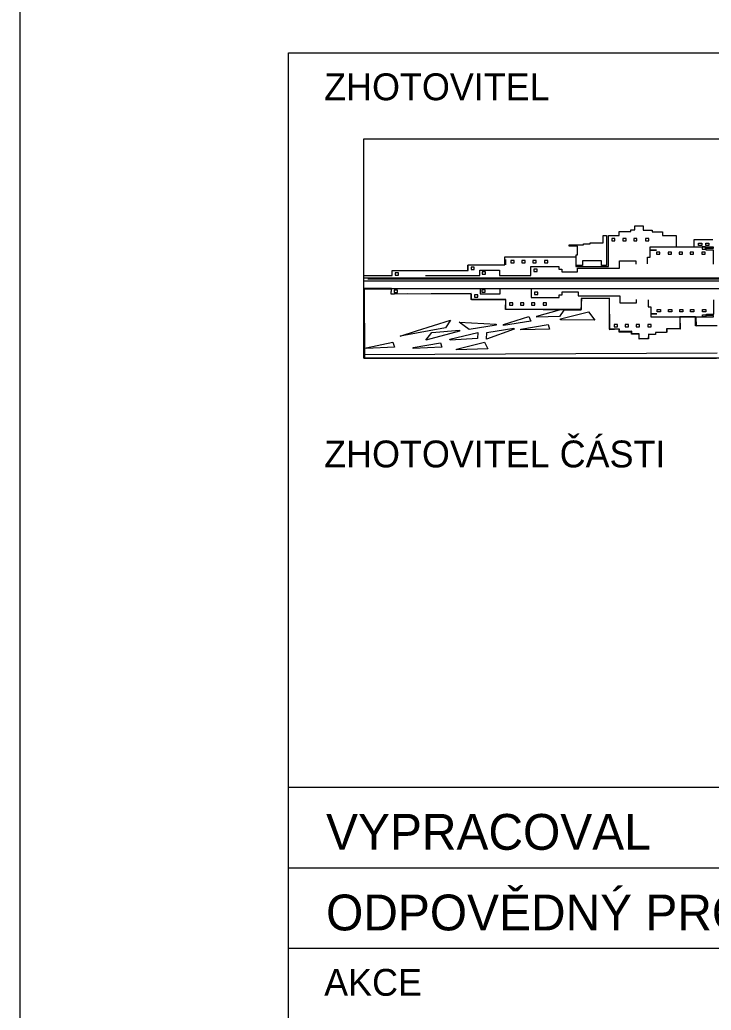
# Model space of a CAD drawing. Extents: x -740053 to -737517, y -1033516 to -1032488.
# Drawn here: x -738610.01 to -738590.71, y -1032656.95 to -1032629.3 of the extents above; entities that cross this region are included whole.
import ezdxf

# ---------------------------------------------------------------- set-up
doc = ezdxf.new("R2010")
doc.units = 0
for name, color, linetype in [('Predmety bez rozlišeni', 7, 'Continuous'), ('promika-formát', 7, 'Continuous'), ('promika-rozp', 7, 'Continuous')]:
    doc.layers.add(name, color=color, linetype=linetype)

# ---------------------------------------------------------------- blocks, each defined once
blk = doc.blocks.new('onegast')
for p, q in [((6.825, 5.723), (6.825, 6.082)), ((9.252, 6.105), (9.252, 6.463)), ((9.309, 6.102), (9.309, 6.46)), ((0.046, 5.264), (49.513, 5.263)), ((0.278, 5.186), (49.435, 5.186)), ((0.046, 5.075), (49.427, 5.075)), ((0.046, 4.561), (49.435, 4.561))]:
    blk.add_line(p, q)
for points in [[(0, 14.352), (49.53, 14.352), (49.53, 0), (0, 0)], [(21.914, 7.53), (22.13, 7.53), (22.13, 7.378), (21.914, 7.378)], [(22.377, 7.53), (22.593, 7.53), (22.593, 7.378), (22.377, 7.378)], [(19.161, 6.799), (19.377, 6.799), (19.377, 6.95), (19.161, 6.95)], [(9.139, 2.21), (10.813, 2.729), (10.929, 2.436), (9.143, 2.148)], [(12.874, 2.574), (14.701, 3.028), (15.132, 2.483), (12.879, 2.512)], [(19.195, 3.182), (19.411, 3.182), (19.411, 3.031), (19.195, 3.031)], [(3.464, 1.792), (5.689, 2.483), (5.353, 1.985), (2.388, 1.451)], [(6.257, 2.359), (8.663, 2.239), (8.678, 2.175), (6.892, 1.886)], [(8.049, 1.674), (9.825, 1.965), (9.84, 1.9), (8.039, 1.247)], [(10.285, 1.911), (12.061, 2.202), (12.15, 1.899), (10.289, 1.849)], [(4.449, 1.687), (6.263, 1.842), (6.277, 1.778), (4.06, 1.174)], [(5.644, 1.239), (7.471, 1.693), (7.457, 1.283), (5.649, 1.176)], [(0.161, 0.692), (1.912, 1.059), (2.012, 0.718), (0.165, 0.63)], [(3.24, 0.71), (5.016, 1), (5.119, 0.715), (3.244, 0.648)], [(6.077, 0.602), (7.903, 1.057), (8.126, 0.622), (6.081, 0.54)]]:
    blk.add_lwpolyline(points, close=True)
for points in [[(0.046, 5.405), (1.862, 5.405), (1.862, 5.731), (6.84, 5.731), (6.84, 6.109), (9.238, 6.109), (9.238, 6.643), (13.878, 6.643), (13.878, 6.005), (16.015, 6.005), (16.015, 8.023), (16.706, 8.023), (16.706, 8.284), (17.475, 8.284), (17.475, 8.401), (17.749, 8.401), (17.749, 8.662), (18.296, 8.662), (18.296, 8.388), (18.879, 8.388), (18.879, 8.272), (19.556, 8.272), (19.556, 8.037), (20.443, 8.037), (20.443, 7.282), (21.616, 7.282), (21.616, 7.764), (22.841, 7.764)], [(14.328, 6.074), (13.905, 6.074), (13.905, 6.765), (14, 6.765), (14, 7.326), (13.453, 7.326), (13.453, 7.425), (14.378, 7.425), (14.378, 7.475), (14.825, 7.475), (14.825, 7.544), (15.233, 7.544), (15.273, 7.544), (15.68, 7.544), (15.68, 8.021), (15.879, 8.021), (15.879, 6.074), (15.571, 6.074), (15.571, 6.362), (14.328, 6.362), (14.328, 6.074)], [(16.228, 7.685), (16.444, 7.685), (16.444, 7.836), (16.228, 7.836), (16.228, 7.685)], [(16.952, 7.685), (17.168, 7.685), (17.168, 7.836), (16.952, 7.836), (16.952, 7.685)], [(17.666, 7.685), (17.882, 7.685), (17.882, 7.836), (17.666, 7.836), (17.666, 7.685)], [(18.439, 7.685), (18.655, 7.685), (18.655, 7.836), (18.439, 7.836), (18.439, 7.685)], [(18.576, 6.169), (18.576, 6.617), (18.746, 6.617), (18.746, 7.081), (19.149, 7.081), (19.149, 7.081), (18.746, 7.081), (18.746, 7.282), (22.862, 7.282), (22.862, 7.282), (22.862, 7.183), (22.396, 7.183), (22.396, 7.088), (22.871, 7.088), (22.871, 6.157)], [(22.141, 7.131), (22.357, 7.131), (22.357, 7.282), (22.141, 7.282), (22.141, 7.131)], [(19.919, 6.799), (20.135, 6.799), (20.135, 6.95), (19.919, 6.95), (19.919, 6.799)], [(20.644, 6.799), (20.86, 6.799), (20.86, 6.95), (20.644, 6.95), (20.644, 6.799)], [(21.358, 6.799), (21.574, 6.799), (21.574, 6.95), (21.358, 6.95), (21.358, 6.799)], [(22.13, 6.799), (22.346, 6.799), (22.346, 6.95), (22.13, 6.95), (22.13, 6.799)], [(4.051, 5.42), (7.596, 5.42), (7.596, 5.765), (8.897, 5.765), (8.897, 5.42), (10.933, 5.42), (10.933, 6.01), (12.761, 6.01), (12.761, 5.826), (12.957, 5.826), (12.957, 5.643), (14, 5.643), (14, 5.888), (16.736, 5.888), (16.736, 6.366), (17.815, 6.366), (17.815, 6.145)], [(7.024, 5.813), (7.24, 5.813), (7.24, 5.964), (7.024, 5.964), (7.024, 5.813)], [(9.628, 6.243), (9.844, 6.243), (9.844, 6.394), (9.628, 6.394), (9.628, 6.243)], [(10.353, 6.243), (10.569, 6.243), (10.569, 6.394), (10.353, 6.394), (10.353, 6.243)], [(11.067, 6.243), (11.283, 6.243), (11.283, 6.394), (11.067, 6.394), (11.067, 6.243)], [(11.131, 5.681), (11.348, 5.681), (11.348, 5.832), (11.131, 5.832), (11.131, 5.681)], [(11.839, 6.243), (12.055, 6.243), (12.055, 6.394), (11.839, 6.394), (11.839, 6.243)], [(2.06, 5.439), (2.276, 5.439), (2.276, 5.591), (2.06, 5.591), (2.06, 5.439)], [(7.749, 5.505), (7.965, 5.505), (7.965, 5.656), (7.749, 5.656), (7.749, 5.505)], [(0.036, 4.579), (0.065, 0.028), (23.119, 0.038)], [(23.133, 2.114), (21.714, 2.114), (21.714, 2.699), (20.694, 2.699), (20.694, 1.928), (19.819, 1.928), (19.819, 1.69), (19.103, 1.69), (19.103, 1.544), (18.625, 1.544), (18.625, 1.266), (18.029, 1.266), (18.029, 1.57), (17.525, 1.57), (17.525, 1.716), (16.716, 1.716), (16.716, 1.902), (16.093, 1.902), (16.093, 3.915), (14.237, 3.915), (14.237, 3.187), (9.292, 3.187), (9.292, 3.849), (7.039, 3.849), (7.039, 4.233), (1.802, 4.196), (1.811, 4.57), (0.036, 4.579)], [(4.084, 4.561), (7.63, 4.561), (7.63, 4.216), (8.93, 4.216), (8.93, 4.561), (10.967, 4.561), (10.967, 3.971), (12.794, 3.971), (12.794, 4.155), (12.991, 4.155), (12.991, 4.339), (14.034, 4.339), (14.034, 4.094), (16.769, 4.094), (16.769, 3.616), (17.849, 3.616), (17.849, 3.836)], [(0.02, 0.014), (23.093, 0.002)], [(23.125, 2.114), (22.3, 2.114), (21.766, 2.106), (21.766, 2.114), (21.714, 2.114), (21.714, 2.69), (20.694, 2.699), (20.694, 2.513), (20.708, 1.897), (19.841, 1.924), (19.841, 1.714), (19.819, 1.714), (19.819, 1.69), (19.163, 1.69), (19.103, 1.687), (19.103, 1.544), (18.635, 1.544), (18.625, 1.386), (18.625, 1.266), (18.256, 1.266), (18.026, 1.258), (18.017, 1.57), (17.525, 1.57), (17.525, 1.716), (16.716, 1.716), (16.716, 1.896), (16.101, 1.86), (16.101, 1.902), (16.093, 1.902), (16.093, 2.719), (16.083, 3.915), (14.514, 3.915), (14.249, 3.911), (14.237, 3.714), (14.237, 3.187), (14.206, 3.187), (14.203, 3.146), (13.089, 3.156), (12.812, 2.735), (11.338, 2.693), (11.334, 2.755), (12.803, 3.159), (9.776, 3.187), (9.292, 3.187), (9.292, 3.191), (9.287, 3.191), (9.292, 3.593), (9.292, 3.82), (7.066, 3.831), (7.065, 3.849), (7.039, 3.849), (7.039, 4.196), (2.893, 4.204), (2.028, 4.198), (1.802, 4.187), (1.803, 4.196), (1.802, 4.196), (1.81, 4.518), (0.042, 4.506), (0.02, 0.014)], [(0.042, 4.506), (0.03, 0.238), (23.125, 0.347)], [(23.125, 2.125), (21.766, 2.106), (21.748, 2.69), (20.689, 2.699), (20.708, 1.897), (19.841, 1.924), (19.841, 1.714), (19.093, 1.687), (19.093, 1.559), (18.637, 1.568), (18.619, 1.277), (18.026, 1.258), (18.017, 1.605), (17.542, 1.596), (17.542, 1.769), (16.721, 1.751), (16.73, 1.897), (16.101, 1.86), (16.083, 3.939), (14.249, 3.911), (14.203, 3.146), (9.287, 3.191), (9.296, 3.82), (7.066, 3.831), (7.048, 4.196), (2.185, 4.205), (1.802, 4.187), (1.821, 4.518), (0.042, 4.506)], [(1.994, 4.298), (2.21, 4.298), (2.21, 4.449), (1.994, 4.449), (1.994, 4.298)], [(7.243, 3.99), (7.46, 3.99), (7.46, 4.142), (7.243, 4.142), (7.243, 3.99)], [(7.727, 4.32), (7.943, 4.32), (7.943, 4.471), (7.727, 4.471), (7.727, 4.32)], [(11.175, 4.166), (11.391, 4.166), (11.391, 4.317), (11.175, 4.317), (11.175, 4.166)], [(9.536, 3.464), (9.752, 3.464), (9.752, 3.615), (9.536, 3.615), (9.536, 3.464)], [(10.26, 3.464), (10.476, 3.464), (10.476, 3.615), (10.26, 3.615), (10.26, 3.464)], [(10.974, 3.464), (11.19, 3.464), (11.19, 3.615), (10.974, 3.615), (10.974, 3.464)], [(11.746, 3.464), (11.963, 3.464), (11.963, 3.615), (11.746, 3.615), (11.746, 3.464)], [(18.61, 3.813), (18.61, 3.364), (18.78, 3.364), (18.78, 2.9), (19.182, 2.9), (19.182, 2.9), (18.78, 2.9), (18.78, 2.699), (22.895, 2.699), (22.895, 2.699), (22.895, 2.799), (22.429, 2.799), (22.429, 2.894), (22.904, 2.894), (22.904, 3.824)], [(9.143, 2.148), (9.139, 2.21), (10.813, 2.729), (10.929, 2.436), (9.143, 2.148)], [(15.132, 2.483), (12.879, 2.512), (12.874, 2.574), (14.701, 3.028), (15.132, 2.483)], [(19.195, 3.031), (19.195, 3.182), (19.411, 3.182), (19.411, 3.031), (19.195, 3.031)], [(20.169, 3.031), (19.953, 3.031), (19.953, 3.182), (20.169, 3.182), (20.169, 3.031)], [(20.893, 3.031), (20.677, 3.031), (20.677, 3.182), (20.893, 3.182), (20.893, 3.031)], [(21.607, 3.031), (21.391, 3.031), (21.391, 3.182), (21.607, 3.182), (21.607, 3.031)], [(22.38, 3.031), (22.164, 3.031), (22.164, 3.182), (22.38, 3.182), (22.38, 3.031)], [(22.39, 2.699), (22.174, 2.699), (22.174, 2.85), (22.39, 2.85), (22.39, 2.699)], [(2.388, 1.451), (3.464, 1.792), (5.689, 2.483), (5.353, 1.985), (2.388, 1.451)], [(6.892, 1.886), (6.257, 2.359), (8.663, 2.239), (8.678, 2.175), (6.892, 1.886)], [(8.039, 1.247), (8.049, 1.674), (9.825, 1.965), (9.84, 1.9), (8.039, 1.247)], [(10.289, 1.849), (10.285, 1.911), (12.061, 2.202), (12.15, 1.899), (10.289, 1.849)], [(16.383, 2.065), (16.599, 2.065), (16.599, 2.216), (16.383, 2.216), (16.383, 2.065)], [(17.107, 2.065), (17.324, 2.065), (17.324, 2.216), (17.107, 2.216), (17.107, 2.065)], [(17.821, 2.065), (18.037, 2.065), (18.037, 2.216), (17.821, 2.216), (17.821, 2.065)], [(18.594, 2.065), (18.81, 2.065), (18.81, 2.216), (18.594, 2.216), (18.594, 2.065)], [(4.06, 1.174), (4.449, 1.687), (6.263, 1.842), (6.277, 1.778), (4.06, 1.174)], [(5.649, 1.176), (5.644, 1.239), (7.471, 1.693), (7.457, 1.283), (5.649, 1.176)], [(0.165, 0.63), (0.161, 0.692), (1.912, 1.059), (2.012, 0.718), (0.165, 0.63)], [(3.244, 0.648), (3.24, 0.71), (5.016, 1), (5.119, 0.715), (3.244, 0.648)], [(6.081, 0.54), (6.077, 0.602), (7.903, 1.057), (8.126, 0.622), (6.081, 0.54)]]:
    blk.add_lwpolyline(points)

msp = doc.modelspace()

# ---------------------------------------------------------------- linework, layer by layer
at = {"layer": 'Predmety bez rozlišeni'}
msp.add_line((-738610.011, -1032536.475), (-738610.011, -1032684.975), dxfattribs=at)
at = {"layer": 'promika-formát'}
msp.add_lwpolyline([(-738610.011, -1032684.975), (-738505.011, -1032684.975), (-738505.011, -1032536.475), (-738610.011, -1032536.475)], close=True, dxfattribs=at)
at = {"layer": 'promika-rozp'}
for p, q in [((-738602.511, -1032650.725), (-738512.511, -1032650.725)), ((-738602.511, -1032652.975), (-738512.511, -1032652.975)), ((-738602.511, -1032655.225), (-738512.511, -1032655.225))]:
    msp.add_line(p, q, dxfattribs=at)
for points in [[(-738602.511, -1032650.725), (-738602.511, -1032630.225), (-738512.511, -1032630.225), (-738512.511, -1032650.725)], [(-738512.511, -1032650.725), (-738512.511, -1032677.475), (-738602.511, -1032677.475), (-738602.511, -1032650.725)], [(-738602.511, -1032655.225), (-738512.511, -1032655.225)]]:
    msp.add_lwpolyline(points, dxfattribs=at)

# ---------------------------------------------------------------- block references
at = {"xscale": 0.4267458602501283, "yscale": 0.4267458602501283}
msp.add_blockref('onegast', (-738600.41, -1032638.753), dxfattribs=at)

# ---------------------------------------------------------------- texts
at = {"layer": 'promika-rozp'}
for s, height, p in [('ZHOTOVITEL', 0.75, (-738601.513, -1032631.55)), ('ZHOTOVITEL ČÁSTI', 0.75, (-738601.513, -1032641.8)), ('VYPRACOVAL', 1, (-738601.46, -1032652.475)), ('ODPOVĚDNÝ PROJEKTANT ČÁSTI', 1, (-738601.46, -1032654.725)), ('AKCE', 0.75, (-738601.513, -1032656.55))]:
    msp.add_text(s, height=height, dxfattribs=at).set_placement(p)

doc.saveas('drawing.dxf')
